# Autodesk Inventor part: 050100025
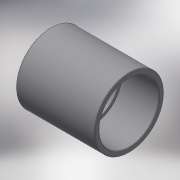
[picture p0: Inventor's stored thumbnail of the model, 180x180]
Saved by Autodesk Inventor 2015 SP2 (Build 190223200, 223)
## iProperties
Created: 2017-10
Part Number: 050100025
Material: Generic
Description: PLASSON SOCKET PVC 25 - CEMENT
Document SubType Name: Modeling
Designer: KIM
Density: 1 g/cm^3
Appearance: Default
Author: KIM
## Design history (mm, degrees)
derived "050100.ipt"
feature "Solid1::050100.ipt"
tag "TaggingFeature1"
body "Solid1"
other parameters: "d0" = 42, "d2" = 19, "d3" = 4, "d4" = 25, "d5" = 22.5, "d7" = 0.25, "d_" = 25, "H_" = 42, "l_" = 19, "Z_" = 4
